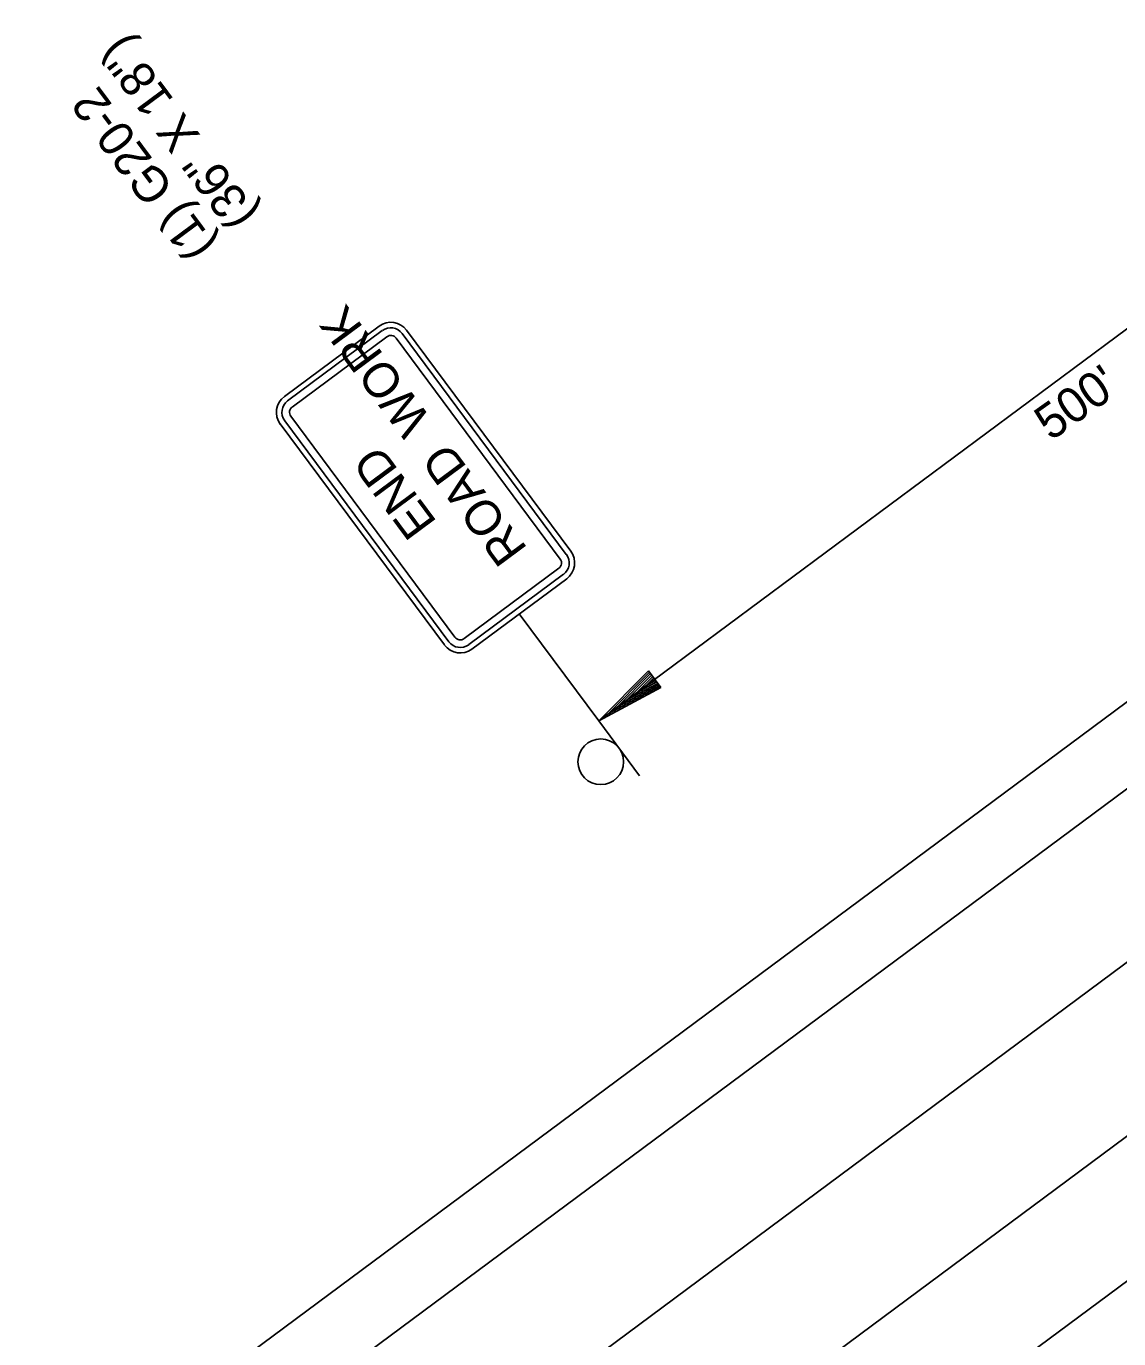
# Model space of a CAD drawing. Extents: x 998982 to 1000626, y 1875366 to 1876934.
# Drawn here: x 999363.4 to 999550.9, y 1875767.2 to 1875992.5 of the extents above; entities that cross this region are included whole.
import ezdxf

# ---------------------------------------------------------------- set-up
doc = ezdxf.new("R2010")
doc.units = 0
for name, color, linetype in [('P_TC_Signs_Temporary', 7, 'Continuous'), ('R_Border Prem', 7, 'Continuous'), ('R_Draft', 7, 'Continuous'), ('STAMP', 7, 'Continuous')]:
    doc.layers.add(name, color=color, linetype=linetype)

msp = doc.modelspace()

# ---------------------------------------------------------------- linework, layer by layer
at = {"layer": 'P_TC_Signs_Temporary'}
for p, q in [((999423.99, 1875941.05), (999407.73, 1875928.98)), ((999424.54, 1875940.3), (999408.29, 1875928.22)), ((999456.88, 1875902.42), (999428.71, 1875940.35)), ((999425.33, 1875939.24), (999409.07, 1875927.17)), ((999455.07, 1875901.08), (999426.9, 1875939.01)), ((999456.12, 1875901.86), (999427.95, 1875939.79)), ((999407.03, 1875924.26), (999435.2, 1875886.32)), ((999407.78, 1875924.81), (999435.95, 1875886.88)), ((999408.84, 1875925.6), (999437.01, 1875887.66)), ((999438.58, 1875887.43), (999454.84, 1875899.5)), ((999439.36, 1875886.38), (999455.62, 1875898.45)), ((999439.92, 1875885.62), (999456.18, 1875897.69))]:
    msp.add_line(p, q, dxfattribs=at)
for centre, radius, start, end in [((999426, 1875938.34), 3.38, 36.5953, 126.5953), ((999426, 1875938.34), 2.44, 36.5953, 126.5953), ((999426, 1875938.34), 1.13, 36.5953, 126.5953), ((999409.74, 1875926.27), 3.38, 126.5953, 216.5953), ((999409.74, 1875926.27), 2.44, 126.5953, 216.5953), ((999409.74, 1875926.27), 1.13, 126.5953, 216.5953), ((999454.17, 1875900.4), 2.44, 306.5953, 36.5953), ((999454.17, 1875900.4), 3.38, 306.5953, 36.5953), ((999454.17, 1875900.4), 1.13, 306.5953, 36.5953), ((999437.91, 1875888.33), 3.38, 216.5953, 306.5953), ((999437.91, 1875888.33), 2.44, 216.5953, 306.5953), ((999437.91, 1875888.33), 1.13, 216.5953, 306.5953)]:
    msp.add_arc(centre, radius, start, end, dxfattribs=at)
at = {"layer": 'R_Draft'}
for p, q in [((999461.67, 1875873.31), (999622.25, 1875992.54)), ((999192.61, 1875564.71), (999743.69, 1875973.9)), ((999171.2, 1875593.53), (999643.2, 1875944.01)), ((999178.34, 1875583.93), (999650.33, 1875934.4)), ((999206.88, 1875545.49), (999678.87, 1875895.96)), ((999461.67, 1875873.31), (999448.05, 1875891.66)), ((999470.21, 1875881.89), (999461.67, 1875873.31)), ((999470.39, 1875881.65), (999463.28, 1875874.5)), ((999470.57, 1875881.4), (999464.93, 1875875.73)), ((999472.35, 1875879), (999470.21, 1875881.89)), ((999218.77, 1875529.47), (999690.77, 1875879.94)), ((999472.18, 1875879.24), (999463.28, 1875874.5)), ((999471.99, 1875879.49), (999464.93, 1875875.73)), ((999470.75, 1875881.16), (999466.53, 1875876.92)), ((999471.82, 1875879.73), (999466.53, 1875876.92)), ((999470.94, 1875880.91), (999468.16, 1875878.13)), ((999471.63, 1875879.98), (999468.16, 1875878.13)), ((999471.12, 1875880.67), (999469.77, 1875879.32)), ((999471.45, 1875880.22), (999469.77, 1875879.32)), ((999472.35, 1875879), (999461.67, 1875873.31))]:
    msp.add_line(p, q, dxfattribs=at)
at = {"layer": 'STAMP'}
msp.add_line((999461.67, 1875873.31), (999468.68, 1875863.87), dxfattribs=at)
msp.add_circle((999462.03, 1875866.26), 3.92, dxfattribs=at)

# ---------------------------------------------------------------- texts
at = {"layer": 'P_TC_Signs_Temporary'}
for s, p in [('ROAD  WORK', (999449.58, 1875902.81)), ('END', (999434.04, 1875907.38))]:
    msp.add_text(s, height=6, rotation=126.5953, dxfattribs=at).set_placement(p)
at = {"layer": 'R_Border Prem'}
for s, rotation, p in [('(36" X 18")', 126.5953, (999403.37, 1875960.39)), ('(1) G20-2', 126.5953, (999396.14, 1875955.02)), ("500'", 35.3649, (999539.27, 1875921.23))]:
    msp.add_text(s, height=6, rotation=rotation, dxfattribs=at).set_placement(p)

doc.saveas('drawing.dxf')
